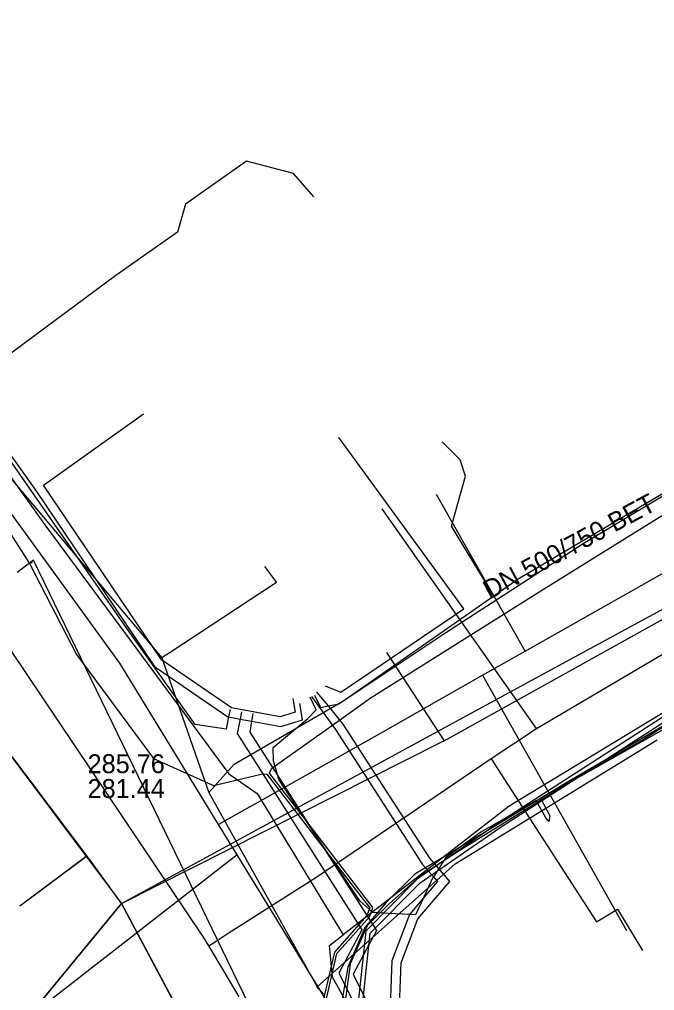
# Model space of a CAD drawing. Extents: x -600309 to -598967, y -1161267 to -1160292.
# Drawn here: x -599910.47 to -599883.55, y -1160480.7 to -1160439.56 of the extents above; entities that cross this region are included whole.
import ezdxf

# ---------------------------------------------------------------- set-up
doc = ezdxf.new("R2010")
doc.units = 0
for name, color, linetype in [('Vrstva 1', 7, 'Continuous'), ('Vrstva 12', 7, 'Continuous'), ('Vrstva 13', 7, 'Continuous'), ('Vrstva 16', 7, 'Continuous'), ('Vrstva 42', 7, 'Continuous'), ('Vrstva 44', 7, 'Continuous'), ('Vrstva 54', 7, 'Continuous'), ('Vrstva 55', 7, 'Continuous'), ('Vrstva 9', 7, 'Continuous')]:
    doc.layers.add(name, color=color, linetype=linetype)

msp = doc.modelspace()

# ---------------------------------------------------------------- linework, layer by layer
at = {"layer": 'Vrstva 1'}
msp.add_line((-599910.45, -1160477.11), (-599907.643, -1160475.007), dxfattribs=at)
for points in [[(-599857.52, -1160559.89), (-599866.111, -1160548.18), (-599871.76, -1160540.48), (-599878.734, -1160527.773), (-599886.327, -1160513.932), (-599890.764, -1160505.846), (-599893.889, -1160500), (-599898.969, -1160490.471), (-599901.936, -1160484.905), (-599902.158, -1160484.489), (-599906.15, -1160477), (-599907.435, -1160475.222), (-599915.237, -1160464.873), (-599922.471, -1160455.22), (-599931.32, -1160443.41), (-599941.55, -1160433.12), (-599946.993, -1160427.644), (-599952.415, -1160422.19), (-599953.381, -1160421.219)], [(-599936.77, -1160515.36), (-599924.619, -1160500), (-599912.97, -1160485.28), (-599906.15, -1160477), (-599900, -1160473.661), (-599888.1, -1160467.2), (-599867.24, -1160455.88)], [(-599910.45, -1160477.11), (-599907.64, -1160475.01)]]:
    msp.add_lwpolyline(points, dxfattribs=at)
at = {"layer": 'Vrstva 12'}
for points in [[(-599890.37, -1160463.98), (-599889.34, -1160463.25), (-599883.29, -1160459.68), (-599875.71, -1160455.37), (-599868.47, -1160451.58)], [(-599914.89, -1160453.7), (-599911.12, -1160458.67), (-599904.43, -1160466.6)], [(-599890.37, -1160463.98), (-599892.16, -1160461.02), (-599891.57, -1160458.91), (-599891.79, -1160458.21), (-599892.56, -1160457.45)], [(-599900.08, -1160462.73), (-599899.58, -1160463.41), (-599904.08, -1160466.37)], [(-599902.45, -1160472.31), (-599901.37, -1160471.1), (-599896.76, -1160468.44), (-599890.37, -1160463.98)], [(-599904.08, -1160466.37), (-599904.43, -1160466.6)], [(-599904.43, -1160466.6), (-599902.7, -1160471.58)], [(-599897.86, -1160480.54), (-599892, -1160475.33), (-599883.44, -1160470.08)], [(-599902.7, -1160471.58), (-599902.45, -1160472.31)], [(-599902.45, -1160472.31), (-599897.86, -1160480.54)], [(-599897.58, -1160480.85), (-599897.86, -1160480.54)]]:
    msp.add_lwpolyline(points, dxfattribs=at)
at = {"layer": 'Vrstva 13'}
for q in [(-599902.667, -1160478.427), (-599902.13, -1160478.6)]:
    msp.add_line((-599902.44, -1160478.8), q, dxfattribs=at)
for points in [[(-599902.667, -1160478.427), (-599912.9, -1160463.23), (-599924.79, -1160447.56), (-599925.44, -1160446.75), (-599932.72, -1160438.46), (-599934.77, -1160436.27), (-599943.79, -1160426.66), (-599947.29, -1160423.32), (-599949.5, -1160421.29), (-599951.54, -1160419.4), (-599963.13, -1160409.31), (-599964.22, -1160408.49)], [(-599897.91, -1160475.9), (-599890.48, -1160470.86), (-599888.563, -1160469.598), (-599877.58, -1160463.13), (-599872.23, -1160460.28), (-599866.81, -1160457.55), (-599860.035, -1160454.342), (-599858.86, -1160453.81), (-599858.17, -1160453.46), (-599855.87, -1160452.4), (-599849.983, -1160449.842), (-599844.73, -1160447.71), (-599839.08, -1160445.59), (-599836.007, -1160444.443), (-599833.36, -1160443.55), (-599827.64, -1160441.64), (-599821.79, -1160439.96), (-599815.9, -1160438.51), (-599808.369, -1160436.756), (-599797.3, -1160434.741), (-599796.11, -1160434.53), (-599786.36, -1160432.84), (-599780.3, -1160431.87), (-599778.69, -1160431.87)], [(-599897.99, -1160447.07), (-599898.86, -1160446.09), (-599900.85, -1160445.56), (-599903.44, -1160447.39), (-599903.77, -1160448.57), (-599906.38, -1160450.4), (-599913.3, -1160455.51), (-599909.4, -1160460.96), (-599908.59, -1160462.05)], [(-599858.98, -1160455.76), (-599860.1, -1160456.27), (-599869.67, -1160461.06), (-599876.02, -1160464.58), (-599889.71, -1160472.89), (-599896.75, -1160478.33)], [(-599888.563, -1160469.598), (-599888.726, -1160469.354), (-599895.095, -1160460.29)], [(-599908.59, -1160462.05), (-599905.74, -1160465.91)], [(-599905.74, -1160465.91), (-599901.6, -1160471.52), (-599900.4, -1160472.35), (-599896.75, -1160478.33)], [(-599890.48, -1160470.86), (-599890.349, -1160471.07), (-599886.02, -1160477.78), (-599885.12, -1160477.24), (-599884.062, -1160479.004)], [(-599902.13, -1160478.6), (-599901.63, -1160478.26), (-599897.91, -1160475.9)], [(-599895.97, -1160482.33), (-599897.21, -1160480.12), (-599897.33, -1160478.78), (-599896.75, -1160478.33)], [(-599901.16, -1160480.96), (-599901.8, -1160479.88), (-599902.44, -1160478.8)]]:
    msp.add_lwpolyline(points, dxfattribs=at)
at = {"layer": 'Vrstva 16'}
for points in [[(-599902.03, -1160473.66), (-599906.22, -1160466.83), (-599917.21, -1160451.71), (-599919.38, -1160448.9), (-599921.83, -1160445.73), (-599925.66, -1160440.77), (-599928.37, -1160437.95), (-599940.64, -1160425.22), (-599945.97, -1160419.69), (-599950.21, -1160416.11), (-599950.59, -1160415.79), (-599965.19, -1160403.5)], [(-599900.7, -1160472.91), (-599895.44, -1160469.94), (-599890.85, -1160467.34), (-599889.04, -1160466.32), (-599871.21, -1160456.24), (-599860.77, -1160451.74), (-599858.17, -1160450.61), (-599854.01, -1160448.82), (-599850.22, -1160447.18), (-599839.32, -1160442.47), (-599829.86, -1160439.79), (-599810.5, -1160434.28), (-599809.75, -1160434.07), (-599807.51, -1160433.43), (-599804.5, -1160432.88), (-599798.57, -1160431.77), (-599794.9, -1160431.09), (-599789.412, -1160429.772), (-599788.733, -1160429.537)], [(-599889.04, -1160466.32), (-599892.79, -1160459.68)], [(-599890.85, -1160467.34), (-599884.74, -1160478.15)], [(-599900.7, -1160472.91), (-599902.03, -1160473.66)], [(-599901.24, -1160474.94), (-599902.03, -1160473.66)], [(-599901.24, -1160474.94), (-599909.21, -1160481.14)], [(-599849.46, -1160559.23), (-599850.48, -1160557.69), (-599854.8, -1160552.96), (-599856.97, -1160550.57), (-599863.99, -1160540.67), (-599864.73, -1160539.35), (-599865.96, -1160537.14), (-599868.12, -1160533.28), (-599870.32, -1160529.26), (-599872.48, -1160525.48), (-599872.99, -1160524.56), (-599875.15, -1160520.7), (-599877.76, -1160516.03), (-599879.03, -1160513.76), (-599887.17, -1160499.19), (-599895.46, -1160484.36), (-599901.24, -1160474.94)]]:
    msp.add_lwpolyline(points, dxfattribs=at)
at = {"layer": 'Vrstva 42'}
for points in [[(-599944.576, -1160419.52), (-599938.102, -1160425.728), (-599935.965, -1160427.907), (-599932.722, -1160431.19), (-599930.492, -1160433.533), (-599925.031, -1160439.847), (-599924.915, -1160439.799), (-599924.503, -1160439.626), (-599924.479, -1160439.616), (-599924.475, -1160439.659), (-599924.469, -1160439.714), (-599924.796, -1160440.105), (-599924.738, -1160440.175), (-599916.015, -1160450.776), (-599909.783, -1160459.515), (-599904.744, -1160466.968), (-599901.637, -1160469.096), (-599901.605, -1160469.102), (-599901.121, -1160469.192), (-599900.63, -1160469.284), (-599899.399, -1160469.513), (-599898.477, -1160469.231), (-599898.587, -1160468.537)], [(-599901.545, -1160468.794), (-599901.605, -1160469.102), (-599901.707, -1160469.629), (-599903.029, -1160469.427), (-599905.911, -1160465.379), (-599912.327, -1160456.138), (-599917.405, -1160449.649), (-599925.1, -1160440.492), (-599924.738, -1160440.175), (-599924.333, -1160439.82), (-599924.465, -1160439.67), (-599924.475, -1160439.659), (-599924.503, -1160439.626), (-599924.596, -1160439.519), (-599924.915, -1160439.799), (-599925.358, -1160440.186), (-599928.401, -1160436.564), (-599934.917, -1160429.794), (-599943.124, -1160421.628), (-599945.025, -1160419.86)], [(-599897.97, -1160468.177), (-599897.719, -1160468.709), (-599897.378, -1160468.64), (-599896.94, -1160468.55), (-599892.48, -1160465.59), (-599886.58, -1160461.76), (-599880.32, -1160458.02), (-599875.17, -1160455.16), (-599869.26, -1160452.22), (-599862.6, -1160448.93), (-599855.26, -1160445.54), (-599848.263, -1160442.648), (-599848.532, -1160442.094), (-599848.53, -1160441.87), (-599848.353, -1160442.006), (-599848.076, -1160442.575), (-599840.88, -1160439.88)], [(-599898.88, -1160468.318), (-599898.788, -1160468.908), (-599899.422, -1160469.102), (-599901.48, -1160468.719), (-599904.456, -1160466.681), (-599909.452, -1160459.291), (-599905.218, -1160456.268)], [(-599897.515, -1160467.784), (-599896.844, -1160468.058), (-599891.634, -1160464.52), (-599896.939, -1160457.265)], [(-599880.1, -1160467.59), (-599884.03, -1160470.06), (-599888.393, -1160472.55), (-599887.989, -1160473.287), (-599888.03, -1160473.53), (-599888.164, -1160473.383), (-599888.567, -1160472.649), (-599890.91, -1160473.98), (-599892.41, -1160475.07), (-599892.704, -1160475.527), (-599892.93, -1160475.878), (-599892.97, -1160475.94), (-599893.35, -1160476.77), (-599893.68, -1160477.49), (-599893.941, -1160477.476), (-599894.83, -1160477.43), (-599895.5, -1160477.39), (-599896.05, -1160476.89), (-599898.117, -1160473.799), (-599899.48, -1160471.76), (-599899.524, -1160471.599), (-599899.7, -1160470.96), (-599899.72, -1160470.4), (-599898.25, -1160469.17), (-599897.895, -1160468.806), (-599898.15, -1160468.263)], [(-599881.537, -1160505.18), (-599882.027, -1160505.322), (-599882.104, -1160505.183), (-599882.299, -1160504.834), (-599887.033, -1160496.355), (-599889.344, -1160492.231), (-599893.42, -1160484.816), (-599894.389, -1160482.068), (-599894.287, -1160479.514), (-599893.584, -1160477.661), (-599892.232, -1160476.076), (-599892.704, -1160475.527), (-599893.079, -1160475.09), (-599896.746, -1160469.406), (-599897.378, -1160468.64), (-599897.861, -1160468.054)], [(-599898.093, -1160468.234), (-599897.076, -1160469.634), (-599893.383, -1160475.351), (-599892.93, -1160475.878), (-599892.759, -1160476.077), (-599893.35, -1160476.77), (-599893.932, -1160477.452), (-599893.941, -1160477.476), (-599894.683, -1160479.434), (-599894.791, -1160482.13), (-599893.77, -1160485.027), (-599893.779, -1160485.033), (-599896.189, -1160486.487), (-599905.598, -1160489.53), (-599905.951, -1160489.556), (-599906.697, -1160489.611), (-599907.648, -1160489.349), (-599908.503, -1160490.567)], [(-599901.059, -1160468.893), (-599901.121, -1160469.192), (-599901.248, -1160469.803), (-599895.964, -1160478.124), (-599896.933, -1160479.964), (-599895.557, -1160482.696), (-599905.951, -1160489.556), (-599906.024, -1160489.604), (-599907.54, -1160490.509), (-599908.695, -1160491.198), (-599908.802, -1160491.981)], [(-599900.575, -1160468.964), (-599900.63, -1160469.284), (-599900.71, -1160469.749), (-599899.524, -1160471.599), (-599898.633, -1160472.99), (-599898.117, -1160473.799), (-599895.342, -1160478.147), (-599896.332, -1160479.993), (-599894.263, -1160484.169), (-599893.779, -1160485.033), (-599884.349, -1160501.878), (-599882.65, -1160505.026), (-599882.299, -1160504.834), (-599881.866, -1160504.597), (-599881.77, -1160504.773), (-599881.674, -1160504.948), (-599882.104, -1160505.183), (-599882.46, -1160505.378), (-599880.011, -1160509.913), (-599875.385, -1160518.214)]]:
    msp.add_lwpolyline(points, dxfattribs=at)
at = {"layer": 'Vrstva 44'}
for points in [[(-599831.479, -1160445.106), (-599847.354, -1160451.095), (-599850.775, -1160452.386), (-599853.888, -1160453.748), (-599860.7, -1160456.899), (-599872.104, -1160462.621), (-599880.709, -1160467.503), (-599890.213, -1160473.616), (-599890.698, -1160473.954), (-599892.636, -1160475.303), (-599893.612, -1160475.982), (-599895.793, -1160478.173), (-599896.108, -1160481.056), (-599895.731, -1160482.616), (-599894.216, -1160484.921), (-599893.728, -1160485.738)], [(-599893.552, -1160485.642), (-599894.044, -1160484.819), (-599895.543, -1160482.542), (-599895.906, -1160481.042), (-599895.601, -1160478.265), (-599893.482, -1160476.136), (-599890.101, -1160473.782), (-599887.031, -1160471.808), (-599885.845, -1160471.045), (-599880.605, -1160467.675), (-599872.01, -1160462.797), (-599871.851, -1160462.717), (-599860.878, -1160457.211), (-599860.614, -1160457.079), (-599860.412, -1160456.986), (-599853.806, -1160453.93), (-599850.699, -1160452.572), (-599847.098, -1160451.213), (-599833.159, -1160445.953)], [(-599881.88, -1160468.72), (-599885.845, -1160471.045), (-599887.32, -1160471.91), (-599890.698, -1160473.954), (-599892.08, -1160474.79), (-599893.71, -1160475.77), (-599894.93, -1160476.97), (-599895.84, -1160478.03), (-599896.55, -1160479.7), (-599896.85, -1160481.37)], [(-599881.75, -1160468.83), (-599887.031, -1160471.808), (-599887.23, -1160471.92), (-599891.92, -1160474.83), (-599892.636, -1160475.303), (-599893.51, -1160475.88), (-599894.8, -1160477.02), (-599895.73, -1160477.95), (-599896.45, -1160479.56), (-599896.67, -1160481.15)]]:
    msp.add_lwpolyline(points, dxfattribs=at)
at = {"layer": 'Vrstva 54'}
for points in [[(-599909.88, -1160462.47), (-599910.565, -1160462.986)], [(-599898.31, -1160486.33), (-599909.88, -1160462.47)]]:
    msp.add_lwpolyline(points, dxfattribs=at)
at = {"layer": 'Vrstva 55'}
for points in [[(-599927.91, -1160439.42), (-599924.89, -1160443.42), (-599917.68, -1160452.83), (-599912.25, -1160460.1), (-599911.269, -1160460.68), (-599910.07, -1160462.56), (-599909.93, -1160462.56), (-599910.05, -1160462.606), (-599908.06, -1160466.46), (-599904.79, -1160470.86), (-599902.25, -1160472.01), (-599900.17, -1160471.51), (-599899.993, -1160471.53), (-599896.042, -1160476.654), (-599895.628, -1160477.191), (-599895.743, -1160477.509), (-599897.125, -1160479.073), (-599897.682, -1160481.472)], [(-599839.19, -1160439.81), (-599846.57, -1160442.55), (-599848.66, -1160443.31), (-599849.71, -1160443.58), (-599853.09, -1160445.05), (-599861.1, -1160448.65), (-599867.44, -1160451.77), (-599874.53, -1160455.49), (-599881.28, -1160459.37), (-599888.37, -1160463.77), (-599895.45, -1160468.22)], [(-599897.05, -1160483.032), (-599897.133, -1160482.82), (-599897.558, -1160481.468), (-599897.015, -1160479.13), (-599895.637, -1160477.571), (-599895.492, -1160477.169), (-599898.477, -1160473.299), (-599899.879, -1160471.48), (-599899.77, -1160471.27), (-599897.008, -1160469.306), (-599895.55, -1160468.27), (-599895.45, -1160468.22)]]:
    msp.add_lwpolyline(points, dxfattribs=at)
at = {"layer": 'Vrstva 9'}
for p, q in [((-599894.915, -1160466.377), (-599892.47, -1160470.11)), ((-599906.15, -1160477), (-599912.97, -1160485.28))]:
    msp.add_line(p, q, dxfattribs=at)
for points in [[(-599931.32, -1160443.41), (-599927.434, -1160448.596), (-599927.212, -1160448.892), (-599926.283, -1160450.132), (-599924.974, -1160451.879), (-599922.027, -1160455.812), (-599915.288, -1160464.805), (-599915.237, -1160464.873), (-599907.585, -1160475.085), (-599906.15, -1160477)], [(-599906.15, -1160477), (-599892.605, -1160470.178), (-599892.47, -1160470.11), (-599871.614, -1160458.523), (-599870.793, -1160458.066), (-599867.2, -1160456.07)], [(-599906.15, -1160477), (-599901.97, -1160484.841), (-599901.612, -1160485.512), (-599898.973, -1160490.463), (-599898.969, -1160490.471), (-599891.08, -1160505.27)]]:
    msp.add_lwpolyline(points, dxfattribs=at)

# ---------------------------------------------------------------- texts
at = {"layer": 'Vrstva 12'}
msp.add_text('DN 500/750 BET', height=0.8, rotation=28.2468, dxfattribs=at).set_placement((-599890.546, -1160464.139))
for s, p in [('285.76', (-599907.583, -1160471.486)), ('281.44', (-599907.583, -1160472.536))]:
    msp.add_text(s, height=0.8, dxfattribs=at).set_placement(p)

doc.saveas('drawing.dxf')
